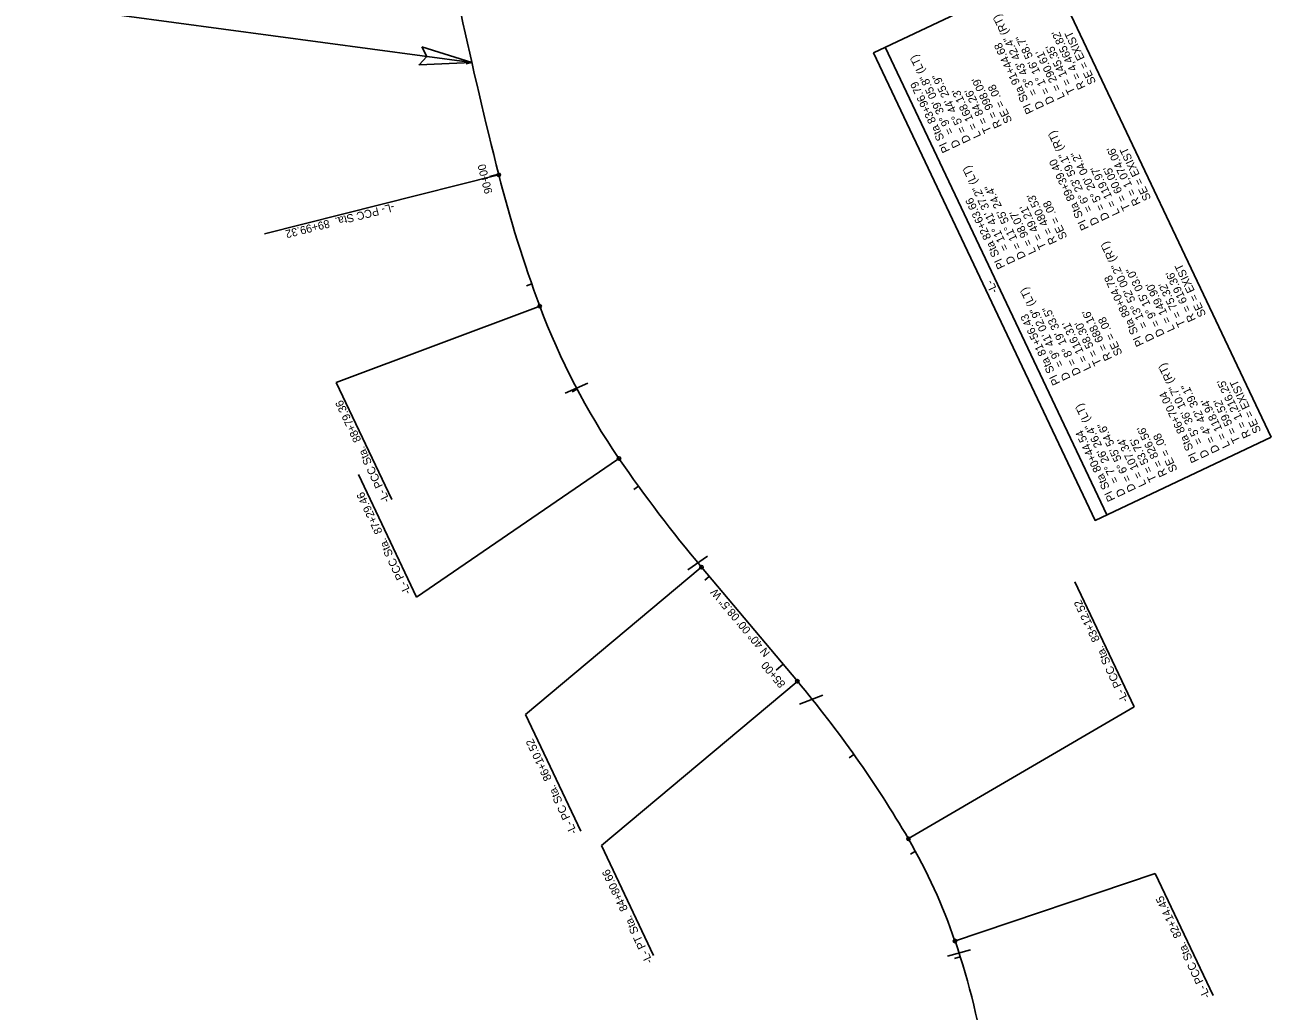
# Model space of a CAD drawing. Extents: x 1019959 to 1023888, y 635993 to 644996.
# Drawn here: x 1022260 to 1023345, y 641128 to 641988 of the extents above; entities that cross this region are included whole.
import ezdxf

# ---------------------------------------------------------------- set-up
doc = ezdxf.new("R2010")
doc.units = 0
for name, color, linetype in [('Cogo Default Point CELL', 7, 'Continuous'), ('COGO Default Point Elevation', 7, 'Continuous'), ('COGO Default Point Number', 7, 'Continuous'), ('Exist Other Culture Well CELL', 7, 'Continuous'), ('Exist Roads EOT', 7, 'Continuous'), ('Exist Structure Minor Pipes CMP 18 Inch Cogo Comment', 7, 'Continuous'), ('Exist Structure Minor Pipes CMP 18 Inch Cogo Number', 7, 'Continuous'), ('Exist Structure Minor Pipes CMP 24 Inch Cogo Number', 7, 'Continuous'), ('Exist Utilities Power Pole CELL', 7, 'Continuous'), ('Exist Utilities Power Pole Cogo Elevation', 7, 'Continuous'), ('Exist Utilities Power Pole Cogo Number', 7, 'Continuous')]:
    doc.layers.add(name, color=color, linetype=linetype)

msp = doc.modelspace()

# ---------------------------------------------------------------- linework, layer by layer
at = {"layer": 'COGO Default Point Elevation'}
for p, q in [((1022648.9, 641955), (1022644, 641953.9)), ((1022701.1, 641762), (1022696.4, 641760.4)), ((1022740.6, 641670.3), (1022736.2, 641668)), ((1022794, 641585.9), (1022790, 641582.9)), ((1022855.7, 641507.2), (1022851.9, 641504)), ((1022981.8, 641352), (1022977.7, 641349.1)), ((1023035.4, 641267.6), (1023031, 641265.2)), ((1023074.3, 641175.7), (1023069.5, 641174.2))]:
    msp.add_line(p, q, dxfattribs=at)
at = {"layer": 'COGO Default Point Number'}
for p, q in [((1022672.2, 641857.8), (1022664.5, 641855.8)), ((1022920, 641430.6), (1022913.9, 641425.5))]:
    msp.add_line(p, q, dxfattribs=at)
at = {"layer": 'Exist Other Culture Well CELL'}
msp.add_line((1022648.9, 641955), (1022259.6, 642007.4), dxfattribs=at)
at = {"layer": 'Exist Roads EOT'}
for p, q in [((1022670.9, 641856.7), (1022468.3, 641805.7)), ((1022706.7, 641742.1), (1022530.8, 641676.2)), ((1022530.8, 641676.2), (1022579.2, 641574.2)), ((1022775.9, 641609.1), (1022600.8, 641489.2)), ((1022550.2, 641595.9), (1022600.8, 641489.2)), ((1022847.8, 641514.3), (1022695.8, 641386.7)), ((1023174.3, 641502.4), (1023225.8, 641393.6)), ((1022931.3, 641414.8), (1022761.9, 641272.6)), ((1023027.9, 641277.8), (1023225.8, 641393.6)), ((1022695.8, 641386.7), (1022743.8, 641285.3)), ((1022761.9, 641272.6), (1022807.2, 641176.9)), ((1023068.4, 641189), (1023244.2, 641248.3)), ((1023244.2, 641248.3), (1023294.6, 641141.9))]:
    msp.add_line(p, q, dxfattribs=at)
for centre in [(1022672.4, 641857.1), (1022708.1, 641742.6), (1022777.1, 641610), (1022849, 641515.3), (1022932.5, 641415.8), (1023029.2, 641278.5), (1023069.8, 641189.4)]:
    msp.add_circle(centre, 1.5, dxfattribs=at)
at = {"layer": 'Exist Structure Minor Pipes CMP 18 Inch Cogo Comment'}
msp.add_lwpolyline([(1022605.4, 641968.7), (1022648.9, 641955), (1022603, 641953.1), (1022609.8, 641960.3)], close=True, dxfattribs=at)
at = {"layer": 'Exist Structure Minor Pipes CMP 18 Inch Cogo Number'}
msp.add_line((1022932.5, 641415.8), (1022849, 641515.3), dxfattribs=at)
for centre, radius, start, end in [((1027003, 642947.5), 4465.8, 190.4045, 194.1329), ((1023714, 642119.4), 1074.1, 194.1329, 200.5327), ((1023288.1, 641959.9), 619.4, 200.5327, 214.3994), ((1023780.6, 642297.1), 1216.2, 214.3994, 220.0024), ((1022167.9, 640774.2), 998.1, 30.3507, 40.0024), ((1022614.5, 641035.7), 480.5, 18.6571, 30.3507), ((1022417.8, 640969.3), 688.2, 8.9729, 18.6571)]:
    msp.add_arc(centre, radius, start, end, dxfattribs=at)
at = {"layer": 'Exist Structure Minor Pipes CMP 24 Inch Cogo Number'}
for p, q in [((1022730.2, 641666.8), (1022749.9, 641675.7)), ((1022837.2, 641512.8), (1022854.3, 641524.8)), ((1022934.2, 641395.8), (1022954.8, 641403.8)), ((1023063.3, 641176.1), (1023083.3, 641181.7))]:
    msp.add_line(p, q, dxfattribs=at)
at = {"layer": 'Exist Utilities Power Pole CELL'}
msp.add_line((1022932.5, 641415.8), (1022849, 641515.3), dxfattribs=at)
for centre, radius, start, end in [((1027003, 642947.5), 4465.8, 190.4045, 194.1329), ((1023714, 642119.4), 1074.1, 194.1329, 200.5327), ((1023288.1, 641959.9), 619.4, 200.5327, 214.3994), ((1023780.6, 642297.1), 1216.2, 214.3994, 220.0024), ((1022167.9, 640774.2), 998.1, 30.3507, 40.0024), ((1022614.5, 641035.7), 480.5, 18.6571, 30.3507), ((1022417.8, 640969.3), 688.2, 8.9729, 18.6571)]:
    msp.add_arc(centre, radius, start, end, dxfattribs=at)
at = {"layer": 'Exist Utilities Power Pole Cogo Elevation'}
msp.add_line((1023202.1, 641560.8), (1023009.1, 641968.3), dxfattribs=at)
msp.add_lwpolyline([(1023345.1, 641628.5), (1023152.1, 642036), (1022998.8, 641963.4), (1023191.8, 641555.9)], close=True, dxfattribs=at)

# ---------------------------------------------------------------- texts
at = {"layer": 'Cogo Default Point CELL'}
for s, rotation, p in [('90+00', 104.1243, (1022667, 641841.6)), ('85+00', 130.0024, (1022922.6, 641413.6))]:
    msp.add_text(s, height=7, rotation=rotation, dxfattribs=at).set_placement(p)
at = {"layer": 'Exist Roads EOT'}
for s, rotation, p in [('-L- PCC Sta.  89+99.32', 194.1329, (1022580.6, 641832.4)), ('-L- PCC Sta.  88+79.36', 115.343, (1022577.7, 641573.3)), ('-L- PCC Sta.  87+29.46', 115.343, (1022596.2, 641493.3)), ('-L- PCC Sta.  83+12.52', 115.343, (1023221.1, 641399.3)), ('-L- PC Sta.  86+10.52', 115.343, (1022740.8, 641284.3)), ('-L- PT Sta.  84+80.66', 115.343, (1022806.7, 641171.6)), ('-L- PCC Sta.  82+14.45', 115.343, (1023292.4, 641141.3))]:
    msp.add_text(s, height=7, rotation=rotation, dxfattribs=at).set_placement(p)
at = {"layer": 'Exist Utilities Power Pole Cogo Elevation'}
for s, p in [('= 3%%d 43\' 42.4" (RT)', (1023141.8, 641927.9)), ('D = 1%%d 16\' 58.7"', (1023156.6, 641920.6)), ("R = 4,465.82'", (1023183.7, 641933.5)), ('SE = EXIST', (1023192.8, 641937.8)), ('PI Sta 91+44.68', (1023138.6, 641912.1)), ("L = 290.61'", (1023165.7, 641924.9)), ("T = 145.35'", (1023174.7, 641929.2)), ('= 9%%d 39\' 05.8" (LT)', (1023068.9, 641894.1)), ('D = 5%%d 44\' 25.9"', (1023083.7, 641886.8)), ('PI Sta 83+96.79', (1023065.6, 641878.3)), ("R = 998.09'", (1023110.8, 641899.7)), ('SE = .08', (1023119.8, 641904)), ("L = 168.13'", (1023092.7, 641891.1)), ("T = 84.26'", (1023101.8, 641895.4)), ('D', (1023147.6, 641916.4)), ('= 6%%d 23\' 59.1" (RT)', (1023189.8, 641826.5)), ('D', (1023074.7, 641882.6)), ("R = 1,074.06'", (1023231.7, 641832.2)), ('SE = EXIST', (1023240.8, 641836.5)), ('PI Sta 89+39.40', (1023186.5, 641810.8)), ('D = 5%%d 20\' 04.2"', (1023204.6, 641819.3)), ('= 11%%d 41\' 37.2" (LT)', (1023116.9, 641792.7)), ("L = 119.97'", (1023213.6, 641823.6)), ("T = 60.05'", (1023222.7, 641827.9)), ('D = 11%%d 55\' 24.4"', (1023131.7, 641785.5)), ('PI Sta 82+63.66', (1023113.6, 641777)), ("R = 480.53'", (1023158.8, 641798.4)), ('SE = .08', (1023167.8, 641802.7)), ("L = 98.07'", (1023140.7, 641789.8)), ("T = 49.21'", (1023149.7, 641794.1)), ('D', (1023195.6, 641815.1)), ('= 13%%d 52\' 00.2" (RT)', (1023237.8, 641725.2)), ('D', (1023122.6, 641781.3)), ('PI Sta 88+04.78', (1023234.5, 641709.5)), ('D = 9%%d 15\' 03.0"', (1023252.6, 641718)), ("R = 619.36'", (1023279.7, 641730.9)), ('SE = EXIST', (1023288.7, 641735.2)), ('-L-', (1023107.3, 641755.8)), ('= 9%%d 41\' 02.9" (LT)', (1023164.8, 641691.4)), ("L = 149.90'", (1023261.6, 641722.3)), ("T = 75.32'", (1023270.7, 641726.6)), ('D = 8%%d 19\' 33.5"', (1023179.7, 641684.2)), ("R = 688.16'", (1023206.8, 641697.1)), ('PI Sta 81+56.43', (1023161.6, 641675.7)), ("L = 116.31'", (1023188.7, 641688.5)), ("T = 58.30'", (1023197.7, 641692.8)), ('SE = .08', (1023215.8, 641701.4)), ('D', (1023243.6, 641713.8)), ('= 5%%d 36\' 10.7" (RT)', (1023285.8, 641623.9)), ('D', (1023170.6, 641680)), ('D = 4%%d 42\' 39.1"', (1023300.6, 641616.7)), ("R = 1,216.25'", (1023327.7, 641629.6)), ('SE = EXIST', (1023336.7, 641633.8)), ('PI Sta 86+70.04', (1023282.5, 641608.2)), ("L = 118.94'", (1023309.6, 641621)), ("T = 59.52'", (1023318.6, 641625.3)), ('= 7%%d 26\' 26.4" (LT)', (1023212.8, 641590.1)), ('D = 6%%d 55\' 54.6"', (1023227.6, 641582.9)), ('PI Sta 80+44.54', (1023209.6, 641574.4)), ("R = 826.56'", (1023254.7, 641595.8)), ('SE = .08', (1023263.8, 641600)), ("L = 107.34'", (1023236.7, 641587.2)), ("T = 53.75'", (1023245.7, 641591.5)), ('D', (1023291.5, 641612.4)), ('D', (1023218.6, 641578.6))]:
    msp.add_text(s, height=7, rotation=115.343, dxfattribs=at).set_placement(p)
at = {"layer": 'Exist Utilities Power Pole Cogo Number'}
msp.add_text('N 40%%d 00\' 08.5" W', height=7, rotation=130.0024, dxfattribs=at).set_placement((1022909.1, 641440.7))

doc.saveas('drawing.dxf')
